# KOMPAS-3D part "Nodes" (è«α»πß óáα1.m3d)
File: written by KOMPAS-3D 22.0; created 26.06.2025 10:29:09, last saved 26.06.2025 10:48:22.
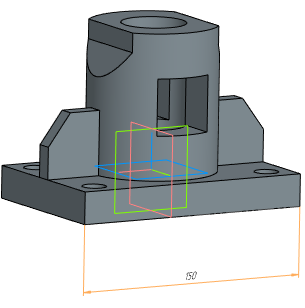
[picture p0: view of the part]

Document properties: Автор: Helen; Полное имя файла: C:\Для ноута\Инженерная графика\ППЭ 2025-2026\Варианты 1-38\Вариант 1 СБ\Вар 1 СБ\Корпус вар1.m3d

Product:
- Body: Тело 1
    Материал: СЧ10 ГОСТ 1412-85 (density 6800 kg/m3)
    Масса: 3.710889
- Body: Тело 2
    Материал: СЧ10 ГОСТ 1412-85 (density 6800 kg/m3)
    Масса: 3.71089
- Part/product: Nodes
    Материал: СЧ10 ГОСТ 1412-85 (density 6800 kg/m3)
    Масса: 7.421778

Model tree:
1. Операция без истории:1
2. Операция без истории:2
3. Эскиз:1  (with: Операция без истории:2)
4. Линейный размер:1  (with: Операция без истории:2)  (labels: СЧ10 ГОСТ 1412-85)
     Значение = 150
